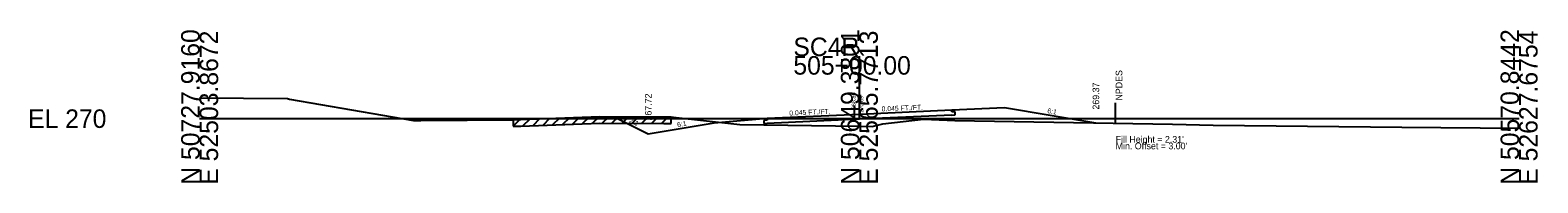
# Model space of a CAD drawing. Extents: x 7498 to 13027, y 90095 to 109625.
# Drawn here: x 8498.3 to 8726.8, y 95095.5 to 95118.5 of the extents above; entities that cross this region are included whole.
import ezdxf

# ---------------------------------------------------------------- set-up
doc = ezdxf.new("R2010")
doc.units = 0
for name, color, linetype in [('Level 10', 7, 'Continuous'), ('Level 11', 7, 'Continuous'), ('Level 12', 7, 'Continuous'), ('Level 32', 7, 'Continuous'), ('Level 33', 7, 'Continuous'), ('Level 50', 7, 'Continuous'), ('Level 55', 7, 'Continuous'), ('Level 59', 7, 'Continuous'), ('Level 6', 7, 'Continuous'), ('Level 60', 7, 'Continuous'), ('Level 61', 7, 'Continuous'), ('Level 63', 7, 'Continuous'), ('Level 7', 7, 'Continuous')]:
    doc.layers.add(name, color=color, linetype=linetype)

msp = doc.modelspace()

# ---------------------------------------------------------------- linework, layer by layer
at = {"layer": 'Level 11'}
for p, q in [((8609.99, 95104.91), (8609.49, 95104.89)), ((8609.49, 95104.89), (8609.49, 95104.41)), ((8609.99, 95105.21), (8609.99, 95104.91)), ((8637.99, 95106.17), (8637.99, 95106.47)), ((8638.49, 95106.2), (8637.99, 95106.17)), ((8637.99, 95105.69), (8638.49, 95105.72)), ((8638.49, 95105.72), (8638.49, 95106.2)), ((8609.49, 95104.41), (8609.99, 95104.43))]:
    msp.add_line(p, q, dxfattribs=at)
at = {"layer": 'Level 12'}
for p, q in [((8623.99, 95105.06), (8609.99, 95104.43)), ((8637.99, 95105.69), (8623.99, 95105.06))]:
    msp.add_line(p, q, dxfattribs=at)
at = {"layer": 'Level 55'}
msp.add_line((8662.84, 95104.53), (8662.84, 95107.53), dxfattribs=at)
at = {"layer": 'Level 59'}
for p, q in [((8609.99, 95105.21), (8623.99, 95105.84)), ((8623.99, 95105.84), (8637.99, 95106.47))]:
    msp.add_line(p, q, dxfattribs=at)
at = {"layer": 'Level 6'}
for p, q in [((8637.99, 95106.47), (8645.99, 95106.83)), ((8601.99, 95104.55), (8609.99, 95105.21))]:
    msp.add_line(p, q, dxfattribs=at)
at = {"layer": 'Level 60'}
for p, q in [((8523.99, 95108.31), (8537.32, 95108.21)), ((8537.32, 95108.21), (8537.63, 95108.11)), ((8537.63, 95108.11), (8556.41, 95104.9)), ((8556.41, 95104.9), (8556.94, 95104.86)), ((8556.94, 95104.86), (8557.54, 95104.86)), ((8557.54, 95104.86), (8571.58, 95105)), ((8571.58, 95105), (8572.7, 95105.03)), ((8572.7, 95105.03), (8584.65, 95105.47)), ((8584.65, 95105.47), (8594.34, 95105.43)), ((8594.34, 95105.43), (8595.45, 95105.44)), ((8595.45, 95105.44), (8596.2, 95105.34)), ((8596.2, 95105.34), (8604.94, 95104.39)), ((8627.56, 95104.36), (8633.69, 95105.09)), ((8633.69, 95105.09), (8638.45, 95104.86)), ((8638.45, 95104.86), (8671.48, 95104.34)), ((8604.94, 95104.39), (8605.85, 95104.27)), ((8605.85, 95104.27), (8623.99, 95104.01)), ((8623.99, 95104.01), (8625.92, 95103.98)), ((8625.92, 95103.98), (8627.56, 95104.36)), ((8671.48, 95104.34), (8677.62, 95104.19)), ((8677.62, 95104.19), (8706.2, 95103.86)), ((8706.2, 95103.86), (8723.99, 95103.74))]:
    msp.add_line(p, q, dxfattribs=at)
at = {"layer": 'Level 61'}
for p, q in [((8572.52, 95105.03), (8571.49, 95104)), ((8571.49, 95105), (8571.49, 95104)), ((8572.7, 95104.03), (8584.65, 95104.47)), ((8574.02, 95105.08), (8572.99, 95104.05)), ((8575.52, 95105.14), (8574.49, 95104.1)), ((8577.02, 95105.19), (8575.99, 95104.15)), ((8578.53, 95105.25), (8577.49, 95104.21)), ((8580.03, 95105.3), (8578.99, 95104.26)), ((8581.53, 95105.35), (8580.49, 95104.32)), ((8583.03, 95105.41), (8581.99, 95104.37)), ((8584.53, 95105.46), (8583.49, 95104.42)), ((8584.65, 95104.47), (8594.34, 95104.43)), ((8585.99, 95105.46), (8584.99, 95104.47)), ((8587.49, 95105.46), (8586.49, 95104.46)), ((8588.99, 95105.45), (8587.99, 95104.45)), ((8590.49, 95105.45), (8589.49, 95104.45)), ((8591.99, 95105.44), (8590.99, 95104.44)), ((8593.49, 95105.44), (8592.49, 95104.44)), ((8595, 95105.44), (8593.99, 95104.43)), ((8595.46, 95104.44), (8595.46, 95105.44)), ((8571.49, 95104), (8571.58, 95104)), ((8571.58, 95104), (8572.7, 95104.03)), ((8594.34, 95104.43), (8595.45, 95104.44)), ((8595.45, 95104.44), (8595.46, 95104.44))]:
    msp.add_line(p, q, dxfattribs=at)
at = {"layer": 'Level 63'}
for p, q in [((8623.99, 95105.16), (8623.99, 95114.62)), ((8523.99, 95105.16), (8623.99, 95105.16)), ((8623.99, 95105.16), (8723.99, 95105.16))]:
    msp.add_line(p, q, dxfattribs=at)
at = {"layer": 'Level 7'}
for p, q in [((8645.99, 95106.83), (8659.85, 95104.53)), ((8586.84, 95105.46), (8591.99, 95102.88)), ((8591.99, 95102.88), (8601.99, 95104.55))]:
    msp.add_line(p, q, dxfattribs=at)

# ---------------------------------------------------------------- texts
at = {"layer": 'Level 10'}
msp.add_text('268.85', height=0.6, rotation=90, dxfattribs=at).set_placement((8623.43, 95106.58))
at = {"layer": 'Level 32'}
for s, rotation, p in [('0.045 FT./FT.', 2.5766, (8627.38, 95106.25)), ('2:1', 333.435, (8589.02, 95104.65)), ('6:1', 9.4623, (8596.43, 95103.87)), ('0.045 FT./FT.', 2.5766, (8613.38, 95105.62)), ('6:1', 350.5377, (8652.44, 95106.01))]:
    msp.add_text(s, height=0.75, rotation=rotation, dxfattribs=at).set_placement(p)
at = {"layer": 'Level 33'}
for s, p in [('269.37', (8660.34, 95106.53)), ('267.72', (8592.49, 95104.88))]:
    msp.add_text(s, height=1, rotation=90, dxfattribs=at).set_placement(p)
at = {"layer": 'Level 50'}
msp.add_text(' NPDES', height=1, rotation=90, dxfattribs=at).set_placement((8663.84, 95107.53))
for s, p in [("Fill Height = 2.31' ", (8662.84, 95101.53)), ("Min. Offset = 3.00' ", (8662.84, 95100.53))]:
    msp.add_text(s, height=1, dxfattribs=at).set_placement(p)
at = {"layer": 'Level 59'}
msp.add_text(' 270.69', height=0.6, rotation=90, dxfattribs=at).set_placement((8624.59, 95105.84))
at = {"layer": 'Level 63'}
for s, p in [('N 50727.9160', (8523.99, 95095.16)), ('E 52503.8672', (8526.79, 95095.16)), ('N 50649.3801', (8623.99, 95095.16)), ('E 52565.7713', (8626.79, 95095.16)), ('N 50570.8442', (8723.99, 95095.16)), ('E 52627.6754', (8726.79, 95095.16))]:
    msp.add_text(s, height=2.8, rotation=90, dxfattribs=at).set_placement(p)
for s, p in [('SC4R', (8613.99, 95114.62)), ('505+00.00', (8613.99, 95111.82)), ('EL 270', (8497.99, 95103.76))]:
    msp.add_text(s, height=2.8, dxfattribs=at).set_placement(p)

doc.saveas('drawing.dxf')
